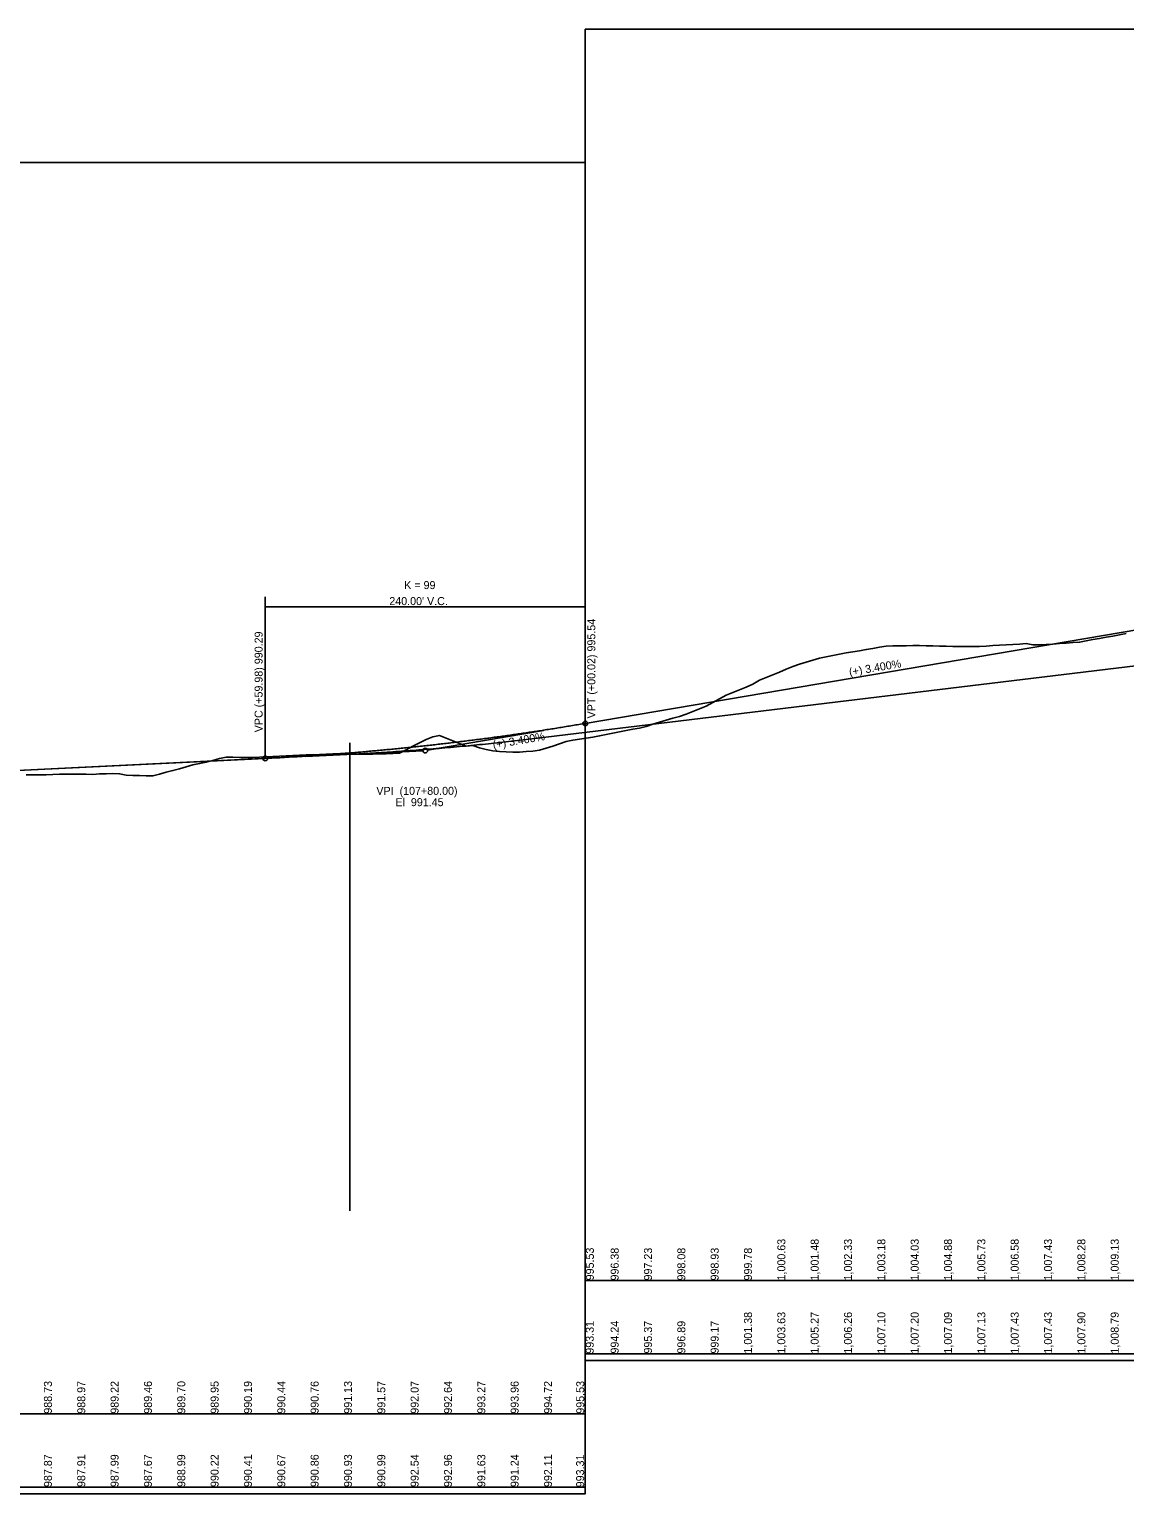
# Model space of a CAD drawing. Extents: x 16972094 to 16980746, y 12563782 to 12565536.
# Drawn here: x 16978503 to 16979324, y 12564438 to 12565536 of the extents above; entities that cross this region are included whole.
import ezdxf

# ---------------------------------------------------------------- set-up
doc = ezdxf.new("R2010")
doc.units = 0
for name, color, linetype in [('Default', 7, 'Continuous'), ('RD_DTM_BkLn1', 7, 'Continuous'), ('RD_EX_BldgChurch', 7, 'Continuous'), ('RD_EX_H2O_Ditch Bottom', 7, 'Continuous'), ('RD_HY_Area_Dtch', 7, 'Continuous'), ('RD_PD_Supershp_I385', 7, 'Continuous'), ('RD_PD_Supershp_Ramp_7', 7, 'Continuous'), ('RD_Sketch2', 7, 'Continuous'), ('RD_Sketch3', 7, 'Continuous'), ('RD_TX_RoadID', 7, 'Continuous'), ('S_HydraCrossSection', 7, 'Continuous')]:
    doc.layers.add(name, color=color, linetype=linetype)

msp = doc.modelspace()

# ---------------------------------------------------------------- linework, layer by layer
at = {"layer": 'Default'}
for points in [[(16978919.9, 12564537.8), (16980419.9, 12564537.8), (16980419.9, 12565536), (16978919.9, 12565536)], [(16977419.9, 12564437.8), (16978919.9, 12564437.8), (16978919.9, 12565436), (16977419.9, 12565436)]]:
    msp.add_lwpolyline(points, close=True, dxfattribs=at)
at = {"layer": 'RD_DTM_BkLn1'}
for p, q in [((16978919.9, 12564597.8), (16980419.9, 12564597.8)), ((16978919.9, 12564542.8), (16980419.9, 12564542.8)), ((16977419.9, 12564497.8), (16978919.9, 12564497.8)), ((16977419.9, 12564442.8), (16978919.9, 12564442.8))]:
    msp.add_line(p, q, dxfattribs=at)
at = {"layer": 'RD_EX_BldgChurch'}
for points in [[(16978985.6, 12565019.3), (16978990.6, 12565020.6), (16978995.6, 12565022.5), (16979000.6, 12565024.4), (16979005.6, 12565026.3), (16979010.6, 12565028.4), (16979015.6, 12565031.1), (16979020.6, 12565034), (16979025.6, 12565036.7), (16979030.6, 12565038.7), (16979035.6, 12565040.7), (16979040.6, 12565042.7), (16979045.6, 12565045), (16979050.6, 12565047.8), (16979055.6, 12565049.9), (16979060.6, 12565051.9), (16979065.6, 12565053.9), (16979070.6, 12565056.2), (16979075.6, 12565058.2), (16979080.6, 12565059.8), (16979085.6, 12565061.3), (16979090.6, 12565062.9), (16979095.6, 12565064.3), (16979100.6, 12565065.4), (16979105.6, 12565066.4), (16979110.6, 12565067.4), (16979115.6, 12565068.3), (16979120.6, 12565069.2), (16979125.6, 12565070), (16979130.6, 12565070.8), (16979135.6, 12565071.7), (16979140.6, 12565072.6), (16979145.6, 12565073.4), (16979150.6, 12565073.6), (16979155.6, 12565073.7), (16979160.6, 12565073.7), (16979165.6, 12565073.8), (16979170.6, 12565073.8), (16979175.6, 12565073.7), (16979180.6, 12565073.6), (16979185.6, 12565073.4), (16979190.6, 12565073.3), (16979195.6, 12565073.2), (16979200.6, 12565073.2), (16979205.6, 12565073.2), (16979210.6, 12565073.2), (16979215.6, 12565073.1), (16979220.6, 12565073.5), (16979225.6, 12565073.8), (16979230.6, 12565074.1), (16979235.6, 12565074.4), (16979240.6, 12565074.7), (16979245.6, 12565075), (16979250.6, 12565075.3), (16979255.6, 12565074.4), (16979260.6, 12565074.3), (16979265.6, 12565074.6), (16979270.6, 12565075), (16979275.6, 12565075.4), (16979280.6, 12565075.7), (16979285.6, 12565076.1), (16979290.6, 12565076.3), (16979295.6, 12565077.4), (16979300.6, 12565078.3), (16979305.6, 12565079.2), (16979310.6, 12565080.1), (16979315.6, 12565081), (16979320.6, 12565081.9), (16979325.6, 12565082.8)], [(16978500.6, 12564976.9), (16978505.6, 12564976.9), (16978510.6, 12564977), (16978515.6, 12564977), (16978520.6, 12564977.1), (16978525.6, 12564977.3), (16978530.6, 12564977.3), (16978535.6, 12564977.4), (16978540.6, 12564977.5), (16978545.6, 12564977.3), (16978550.6, 12564977.2), (16978555.6, 12564977.6), (16978560.6, 12564977.6), (16978565.6, 12564977.9), (16978570.6, 12564977.7), (16978575.6, 12564976.7), (16978580.6, 12564976.5), (16978585.6, 12564976.3), (16978590.6, 12564976.1), (16978595.6, 12564976.1), (16978600.6, 12564977.5), (16978605.6, 12564978.8), (16978610.6, 12564980.1), (16978615.6, 12564981.5), (16978620.6, 12564982.9), (16978625.6, 12564984.4), (16978630.6, 12564985.3), (16978635.6, 12564986.3), (16978640.6, 12564987.6), (16978645.6, 12564989.1), (16978650.6, 12564990.2), (16978655.6, 12564990.2), (16978660.6, 12564989.9), (16978665.6, 12564989.8), (16978670.6, 12564989.9), (16978675.6, 12564990.1), (16978680.6, 12564990.3), (16978685.6, 12564990.6), (16978690.6, 12564990.9), (16978695.6, 12564991.2), (16978700.6, 12564991.5), (16978705.6, 12564991.7), (16978710.6, 12564991.8), (16978715.6, 12564991.9), (16978720.6, 12564992.1), (16978725.6, 12564992.3), (16978730.6, 12564992.6), (16978735.6, 12564992.6), (16978740.6, 12564992.5), (16978745.6, 12564992.4), (16978750.6, 12564992.4), (16978755.6, 12564992.3), (16978760.6, 12564992.4), (16978765.6, 12564992.6), (16978770.6, 12564992.7), (16978775.6, 12564992.9), (16978780.6, 12564993.1), (16978785.6, 12564995.6), (16978790.6, 12564998.3), (16978795.6, 12565000.8), (16978800.6, 12565003.5), (16978805.6, 12565005.3), (16978810.6, 12565006.4), (16978815.6, 12565004.5), (16978820.6, 12565002.3), (16978825.6, 12565000.3), (16978830.6, 12564998.3), (16978835.6, 12564998.8), (16978840.6, 12564997.1), (16978845.6, 12564995.8), (16978850.6, 12564994.8), (16978855.6, 12564994.4), (16978860.6, 12564994.1), (16978865.6, 12564993.9), (16978870.6, 12564994), (16978875.6, 12564994.3), (16978880.6, 12564994.7), (16978885.6, 12564995.4), (16978890.6, 12564996.8), (16978895.6, 12564998.5), (16978900.6, 12565000.2), (16978905.6, 12565001.9), (16978910.6, 12565002.9), (16978915.6, 12565003.7), (16978920.6, 12565004.4), (16978925.6, 12565005.2), (16978930.6, 12565006.1), (16978935.6, 12565007.1), (16978940.6, 12565008.1), (16978945.6, 12565009.1), (16978950.6, 12565010.1), (16978955.6, 12565011.1), (16978960.6, 12565011.9), (16978965.6, 12565013.2), (16978970.6, 12565014.9), (16978975.6, 12565016.5), (16978980.6, 12565018), (16978985.6, 12565019.3)]]:
    msp.add_lwpolyline(points, dxfattribs=at)
at = {"layer": 'RD_EX_H2O_Ditch Bottom'}
for p, q in [((16978888.6, 12565010.1), (16978801.6, 12564995.4)), ((16978710, 12564990.7), (16978798.1, 12564995))]:
    msp.add_line(p, q, dxfattribs=at)
msp.add_circle((16978799.9, 12564995.1), 1.75, dxfattribs=at)
at = {"layer": 'RD_HY_Area_Dtch'}
msp.add_line((16978743.3, 12565000.9), (16978743.3, 12564649.9), dxfattribs=at)
at = {"layer": 'RD_Sketch2'}
for p, q in [((16978919.9, 12565123.2), (16978919.9, 12565017.2)), ((16978679.9, 12565110.5), (16978679.9, 12564991)), ((16978679.9, 12565103), (16978919.9, 12565103))]:
    msp.add_line(p, q, dxfattribs=at)
for centre in [(16978919.9, 12565015.5), (16978679.9, 12564989.2)]:
    msp.add_circle(centre, 1.75, dxfattribs=at)
at = {"layer": 'RD_Sketch3'}
for p, q in [((16978882, 12565004.1), (16979596, 12565090.4)), ((16977879.9, 12564950.3), (16978743.3, 12564992.3))]:
    msp.add_line(p, q, dxfattribs=at)
msp.add_open_spline([(16978743.3, 12564992.3), (16978812.6, 12564995.7), (16978882, 12565004.1)], degree=2, dxfattribs=at)
at = {"layer": 'RD_TX_RoadID'}
for p, q in [((16978919.9, 12565015.5), (16979334.9, 12565086)), ((16978109.9, 12564961.5), (16978679.9, 12564989.2))]:
    msp.add_line(p, q, dxfattribs=at)
msp.add_spline([(16978679.9, 12564989.2), (16978684.7, 12564989.5), (16978689.5, 12564989.7), (16978694.3, 12564990), (16978699.1, 12564990.3), (16978703.9, 12564990.5), (16978708.7, 12564990.8), (16978713.5, 12564991.1), (16978718.3, 12564991.5), (16978723.1, 12564991.8), (16978727.9, 12564992.1), (16978732.7, 12564992.5), (16978737.5, 12564992.9), (16978742.3, 12564993.2), (16978747.1, 12564993.6), (16978751.9, 12564994), (16978756.7, 12564994.5), (16978761.5, 12564994.9), (16978766.3, 12564995.3), (16978771.1, 12564995.8), (16978775.9, 12564996.2), (16978780.7, 12564996.7), (16978785.5, 12564997.2), (16978790.3, 12564997.7), (16978795.1, 12564998.2), (16978799.9, 12564998.7), (16978804.7, 12564999.2), (16978809.5, 12564999.8), (16978814.3, 12565000.3), (16978819.1, 12565000.9), (16978823.9, 12565001.5), (16978828.7, 12565002.1), (16978833.5, 12565002.7), (16978838.3, 12565003.3), (16978843.1, 12565003.9), (16978847.9, 12565004.5), (16978852.7, 12565005.2), (16978857.5, 12565005.8), (16978862.3, 12565006.5), (16978867.1, 12565007.2), (16978871.9, 12565007.9), (16978876.7, 12565008.6), (16978881.5, 12565009.3), (16978886.3, 12565010), (16978891.1, 12565010.8), (16978895.9, 12565011.5), (16978900.7, 12565012.3), (16978905.5, 12565013.1), (16978910.3, 12565013.9), (16978915.1, 12565014.7), (16978919.9, 12565015.5)], degree=3, dxfattribs=at)

# ---------------------------------------------------------------- texts
at = {"layer": 'RD_EX_H2O_Ditch Bottom'}
for s, p in [('VPI  (107+80.00)', (16978763.2, 12564961.9)), ('El  991.45', (16978777.5, 12564953.4))]:
    msp.add_text(s, height=6, dxfattribs=at).set_placement(p)
at = {"layer": 'RD_PD_Supershp_I385'}
for s, p in [('1,000.63', (16979069.9, 12564597.7)), ('1,001.48', (16979094.9, 12564597.7)), ('1,002.33', (16979119.9, 12564597.7)), ('1,003.18', (16979144.9, 12564597.7)), ('1,004.03', (16979169.9, 12564597.7)), ('1,004.88', (16979194.9, 12564597.7)), ('1,005.73', (16979219.9, 12564597.7)), ('1,006.58', (16979244.9, 12564597.7)), ('1,007.43', (16979269.9, 12564597.7)), ('1,008.28', (16979294.9, 12564597.7)), ('1,009.13', (16979319.9, 12564597.7)), ('995.53', (16978926.3, 12564597.8)), ('996.38', (16978944.9, 12564597.7)), ('997.23', (16978969.9, 12564597.7)), ('998.08', (16978994.9, 12564597.7)), ('998.93', (16979019.9, 12564597.7)), ('999.78', (16979044.9, 12564597.7)), ('988.73', (16978519.9, 12564497.8)), ('988.97', (16978544.9, 12564497.8)), ('989.22', (16978569.9, 12564497.8)), ('989.46', (16978594.9, 12564497.8)), ('989.70', (16978619.9, 12564497.8)), ('989.95', (16978644.9, 12564497.8)), ('990.19', (16978669.9, 12564497.8)), ('990.44', (16978694.9, 12564497.8)), ('990.76', (16978719.9, 12564497.8)), ('991.13', (16978744.9, 12564497.8)), ('991.57', (16978769.9, 12564497.8)), ('992.07', (16978794.9, 12564497.8)), ('992.64', (16978819.9, 12564497.8)), ('993.27', (16978844.9, 12564497.8)), ('993.96', (16978869.9, 12564497.8)), ('994.72', (16978894.9, 12564497.8)), ('995.53', (16978919.1, 12564497.8))]:
    msp.add_text(s, height=6, rotation=90, dxfattribs=at).set_placement(p)
at = {"layer": 'RD_PD_Supershp_Ramp_7'}
for s, p in [('1,001.38', (16979044.9, 12564542.9)), ('1,003.63', (16979069.9, 12564542.9)), ('1,005.27', (16979094.9, 12564542.9)), ('1,006.26', (16979119.9, 12564542.9)), ('1,007.10', (16979144.9, 12564542.9)), ('1,007.20', (16979169.9, 12564542.9)), ('1,007.09', (16979194.9, 12564542.9)), ('1,007.13', (16979219.9, 12564542.9)), ('1,007.43', (16979244.9, 12564542.9)), ('1,007.43', (16979269.9, 12564542.9)), ('1,007.90', (16979294.9, 12564542.9)), ('1,008.79', (16979319.9, 12564542.9)), ('993.31', (16978926.2, 12564542.8)), ('994.24', (16978944.9, 12564542.9)), ('995.37', (16978969.9, 12564542.9)), ('996.89', (16978994.9, 12564542.9)), ('999.17', (16979019.9, 12564542.9)), ('987.87', (16978519.9, 12564442.8)), ('987.91', (16978544.9, 12564442.8)), ('987.99', (16978569.9, 12564442.8)), ('987.67', (16978594.9, 12564442.8)), ('988.99', (16978619.9, 12564442.8)), ('990.22', (16978644.9, 12564442.8)), ('990.41', (16978669.9, 12564442.8)), ('990.67', (16978694.9, 12564442.8)), ('990.86', (16978719.9, 12564442.8)), ('990.93', (16978744.9, 12564442.8)), ('990.99', (16978769.9, 12564442.8)), ('992.54', (16978794.9, 12564442.8)), ('992.96', (16978819.9, 12564442.8)), ('991.63', (16978844.9, 12564442.8)), ('991.24', (16978869.9, 12564442.8)), ('992.11', (16978894.9, 12564442.8)), ('993.31', (16978919, 12564442.6))]:
    msp.add_text(s, height=6, rotation=90, dxfattribs=at).set_placement(p)
at = {"layer": 'RD_Sketch2'}
for s, p in [('K = 99', (16978784.1, 12565116.2)), ("240.00' V.C.", (16978772.9, 12565104.2))]:
    msp.add_text(s, height=6, dxfattribs=at).set_placement(p)
for s, p in [('VPT (+00.02) 995.54', (16978927.4, 12565019.2)), ('VPC (+59.98) 990.29', (16978677.9, 12565008.8))]:
    msp.add_text(s, height=6, rotation=90, dxfattribs=at).set_placement(p)
at = {"layer": 'S_HydraCrossSection'}
for p in [(16979118.2, 12565051), (16978851, 12564996.4)]:
    msp.add_text('(+) 3.400%', height=6, rotation=9.6479, dxfattribs=at).set_placement(p)

doc.saveas('drawing.dxf')
